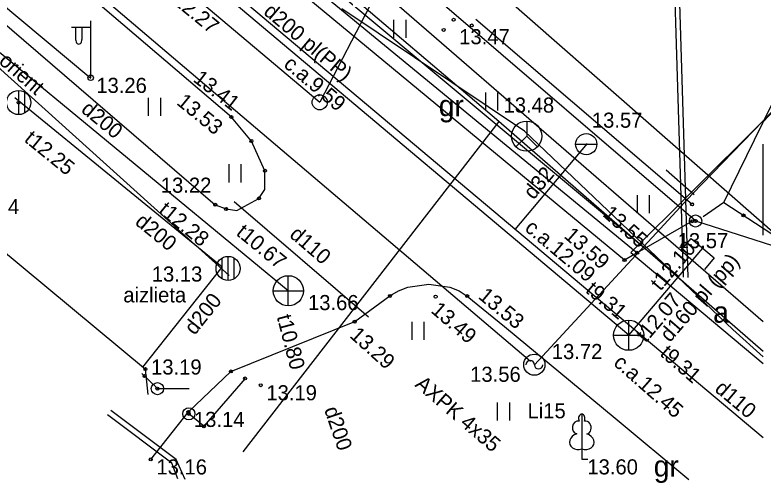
# Model space of a CAD drawing. Extents: x 503877 to 504025, y 304562 to 304725.
# Drawn here: x 503975.24 to 504000, y 304561.64 to 304577.15 of the extents above; entities that cross this region are included whole.
import ezdxf

# ---------------------------------------------------------------- set-up
doc = ezdxf.new("R2010")
doc.units = 0
for name, color, linetype in [('10', 7, 'Continuous'), ('20', 7, 'Continuous'), ('25', 7, 'Continuous'), ('APGS_ACRL_####_####_#', 7, 'Continuous'), ('APGS_ACRL_####_TKST_#', 7, 'Continuous'), ('APGS_ELEM_####_####_#', 7, 'Continuous'), ('APGS_VADP_ZSPR_####_#', 7, 'Continuous'), ('APGS_VADP_ZSPR_TKST_#', 7, 'Continuous'), ('BUVE_BDET_####_####_#', 7, 'Continuous'), ('BUVE_EKAS_####_####_#', 7, 'Continuous'), ('CELI_CAPM_####_####_#', 7, 'Continuous'), ('CELI_CMAL_####_####_#', 7, 'Continuous'), ('CELI_CSEG_####_TKST_#', 7, 'Continuous'), ('CELI_TAKA_####_####_#', 7, 'Continuous'), ('ELEK_VADP_ZSPR_####_#', 7, 'Continuous'), ('ELEK_VADV_ZSPR_####_#', 7, 'Continuous'), ('GAZE_ELEM_####_####_#', 7, 'Continuous'), ('GAZE_ELEM_####_TKST_#', 7, 'Continuous'), ('GAZE_VADP_VSP1_####_#', 7, 'Continuous'), ('GAZE_VADP_VSP2_####_#', 7, 'Continuous'), ('Level 46', 7, 'Continuous'), ('LKAN_ELEM_####_####_#', 7, 'Continuous'), ('LKAN_ELEM_PAST_TKST_#', 7, 'Continuous'), ('LKAN_VADP_PAST_####_#', 7, 'Continuous'), ('LKAN_VADP_PAST_TKST_#', 7, 'Continuous'), ('NORB_ELEM_####_####_#', 7, 'Continuous'), ('NORB_ZOGS_BARJ_####_#', 7, 'Continuous'), ('NORB_ZOGS_ZSTP_####_#', 7, 'Continuous'), ('RAMI_PROB_####_####_#', 7, 'Continuous'), ('RELJ_AATZ_####_TKST_#', 7, 'Continuous'), ('RELJ_ELEM_####_####_#', 7, 'Continuous'), ('SAKK_ELEM_####_####_#', 7, 'Continuous'), ('SAKK_ELEM_####_TKST_#', 7, 'Continuous'), ('SAKK_KKAN_####_####_#', 7, 'Continuous'), ('SAKT_VADP_KABE_####_#', 7, 'Continuous'), ('SAKT_VADP_NEDR_####_#', 7, 'Continuous'), ('SKAN_ELEM_####_####_#', 7, 'Continuous'), ('SKAN_ELEM_PAST_TKST_#', 7, 'Continuous'), ('SKAN_VADP_PAST_####_#', 7, 'Continuous'), ('SKAN_VADP_PAST_####_I', 7, 'Continuous'), ('SKAN_VADP_PAST_TKST_#', 7, 'Continuous'), ('SKAN_VADP_PAST_TKST_I', 7, 'Continuous'), ('SKAN_VADP_SPDK_TKST_I', 7, 'Continuous'), ('TERT_DIAM_####_TKST_#', 7, 'Continuous'), ('TERT_DZOG_####_####_#', 7, 'Continuous'), ('TERT_ELEM_####_####_#', 7, 'Continuous'), ('TERT_KOKR_####_####_#', 7, 'Continuous'), ('TERT_KONT_####_####_#', 7, 'Continuous'), ('UDTK_ELEM_####_####_#', 7, 'Continuous'), ('UDTK_ELEM_####_TKST_#', 7, 'Continuous'), ('UDTK_VADP_NEDR_####_#', 7, 'Continuous'), ('UDTK_VADP_NEDR_TKST_#', 7, 'Continuous'), ('UDTK_VADP_UDEN_####_I', 7, 'Continuous'), ('UDTK_VADP_UDEN_TKST_I', 7, 'Continuous')]:
    doc.layers.add(name, color=color, linetype=linetype)

msp = doc.modelspace()

# ---------------------------------------------------------------- linework, layer by layer
at = {"layer": '10'}
msp.add_circle((503985.325, 304574.255), 0.25, dxfattribs=at)
at = {"layer": '20'}
msp.add_line((503987.744, 304578.935), (503985.325, 304574.255), dxfattribs=at)
at = {"layer": '25'}
msp.add_line((503924.947, 304625.297), (503985.325, 304574.255), dxfattribs=at)
at = {"layer": 'APGS_ACRL_####_####_#'}
msp.add_line((503982.497, 304570.972), (503986.938, 304567.15), dxfattribs=at)
at = {"layer": 'APGS_ELEM_####_####_#'}
for p, q in [((503977.744, 304576.733), (503977.109, 304576.728)), ((503977.244, 304576.729), (503977.244, 304576.337)), ((503977.454, 304576.731), (503977.454, 304576.337)), ((503977.744, 304575.066), (503977.744, 304576.949))]:
    msp.add_line(p, q, dxfattribs=at)
msp.add_circle((503977.744, 304575.066), 0.09, dxfattribs=at)
msp.add_ellipse((503977.349, 304576.337), major_axis=(0, 0.151), ratio=0.695971, start_param=1.570796, end_param=4.712389, dxfattribs=at)
at = {"layer": 'APGS_VADP_ZSPR_####_#'}
msp.add_line((503955.752, 304593.437), (503977.746, 304575.06), dxfattribs=at)
at = {"layer": 'BUVE_BDET_####_####_#'}
msp.add_line((503979.642, 304564.578), (503979.555, 304565.414), dxfattribs=at)
at = {"layer": 'BUVE_EKAS_####_####_#'}
msp.add_line((503973.411, 304570.524), (503979.555, 304565.414), dxfattribs=at)
at = {"layer": 'CELI_CAPM_####_####_#'}
for p, q in [((503982.4, 304573.765), (503968.656, 304585.514)), ((503983.065, 304572.971), (503982.4, 304573.765)), ((503983.513, 304571.985), (503983.065, 304572.971)), ((503983.513, 304571.371), (503983.513, 304571.985)), ((503983.314, 304571.071), (503983.513, 304571.371))]:
    msp.add_line(p, q, dxfattribs=at)
at = {"layer": 'CELI_CMAL_####_####_#'}
for p, q in [((503967.389, 304583.318), (503981.868, 304570.859)), ((503995.414, 304569.03), (503982.055, 304580.09)), ((503982.586, 304570.674), (503983.314, 304571.071)), ((503981.868, 304570.859), (503982.224, 304570.722)), ((503998.706, 304570.932), (503998.022, 304570.456)), ((503998.706, 304570.932), (504000, 304570.084)), ((503982.224, 304570.722), (503982.586, 304570.674)), ((503997.655, 304570.314), (503995.836, 304569.27)), ((503999.782, 304570.227), (504000, 304570.084)), ((504000, 304570.084), (504002.603, 304568.379)), ((503995.836, 304569.27), (503995.414, 304569.03)), ((503987.93, 304568.004), (503988.247, 304568.125)), ((503988.247, 304568.125), (503988.939, 304568.227)), ((503988.939, 304568.227), (503989.627, 304568.134)), ((503989.627, 304568.134), (503989.937, 304568.011)), ((503986.483, 304566.989), (503987.649, 304567.838)), ((503987.649, 304567.838), (503987.93, 304568.004)), ((503989.937, 304568.011), (503990.209, 304567.835)), ((503990.209, 304567.835), (503991.439, 304566.83)), ((503982.384, 304565.337), (503986.483, 304566.989)), ((503991.439, 304566.83), (503995.105, 304563.792)), ((503980.976, 304563.999), (503982.384, 304565.337)), ((503979.734, 304562.425), (503980.976, 304563.999)), ((503995.105, 304563.792), (503997.539, 304561.754))]:
    msp.add_line(p, q, dxfattribs=at)
at = {"layer": 'CELI_TAKA_####_####_#'}
msp.add_line((503982.372, 304580.35), (503995.836, 304569.27), dxfattribs=at)
at = {"layer": 'ELEK_VADP_ZSPR_####_#'}
for p, q in [((503980.425, 304562.304), (503978.298, 304563.903)), ((503980.578, 304562.426), (503978.415, 304564.044)), ((503980.873, 304561.755), (503980.578, 304562.426)), ((503980.629, 304561.786), (503980.425, 304562.304))]:
    msp.add_line(p, q, dxfattribs=at)
at = {"layer": 'ELEK_VADV_ZSPR_####_#'}
msp.add_line((503972.501, 304590.85), (504000, 304566.991), dxfattribs=at)
at = {"layer": 'GAZE_ELEM_####_####_#'}
msp.add_circle((503992.43, 304565.562), 0.35, dxfattribs=at)
for centre, start, end in [((503992.29, 304565.562), 0, 180), ((503992.57, 304565.562), 180, 0)]:
    msp.add_arc(centre, 0.14, start, end, dxfattribs=at)
at = {"layer": 'GAZE_VADP_VSP1_####_#'}
for p, q in [((504002.447, 304576.169), (504000, 304573.64)), ((504000, 304573.604), (504000.37, 304573.991)), ((504000, 304573.64), (503997.664, 304571.226))]:
    msp.add_line(p, q, dxfattribs=at)
at = {"layer": 'GAZE_VADP_VSP2_####_#'}
for p, q in [((503971.829, 304583.093), (503992.301, 304565.684)), ((503997.664, 304571.225), (503992.43, 304565.562))]:
    msp.add_line(p, q, dxfattribs=at)
at = {"layer": 'Level 46'}
msp.add_line((503943.333, 304620.019), (504006.701, 304564.361), dxfattribs=at)
at = {"layer": 'LKAN_ELEM_####_####_#'}
for p, q in [((503975.36, 304573.848), (503975.36, 304574.648)), ((503975.56, 304573.902), (503975.56, 304574.594)), ((503982.093, 304568.405), (503982.093, 304569.097)), ((503982.293, 304568.351), (503982.293, 304569.151)), ((503982.493, 304568.405), (503982.493, 304569.097))]:
    msp.add_line(p, q, dxfattribs=at)
for centre in [(503975.36, 304574.248), (503982.293, 304568.751)]:
    msp.add_circle(centre, 0.4, dxfattribs=at)
at = {"layer": 'LKAN_VADP_PAST_####_#'}
for p, q in [((503982.094, 304568.792), (503975.237, 304574.404)), ((503979.472, 304565.483), (503982.094, 304568.792))]:
    msp.add_line(p, q, dxfattribs=at)
at = {"layer": 'NORB_ELEM_####_####_#'}
for centre in [(503997.768, 304570.323), (503979.953, 304564.768), (503980.991, 304563.932)]:
    msp.add_circle(centre, 0.202, dxfattribs=at)
at = {"layer": 'NORB_ZOGS_BARJ_####_#'}
for p, q in [((503997.768, 304570.323), (504000, 304569.607)), ((504000, 304569.607), (504000.857, 304569.333)), ((503979.953, 304564.768), (503980.999, 304564.768))]:
    msp.add_line(p, q, dxfattribs=at)
at = {"layer": 'NORB_ZOGS_ZSTP_####_#'}
for p, q in [((503997.768, 304570.323), (503987.718, 304578.958)), ((503979.438, 304565.273), (503979.953, 304564.768)), ((503982.856, 304565.105), (503981.489, 304563.521)), ((503981.489, 304563.521), (503980.991, 304563.932))]:
    msp.add_line(p, q, dxfattribs=at)
at = {"layer": 'RAMI_PROB_####_####_#'}
msp.add_line((504000, 304569.849), (504000, 304572.866), dxfattribs=at)
at = {"layer": 'RELJ_ELEM_####_####_#'}
for centre in [(503989.757, 304576.989), (503990.359, 304576.8), (503989.429, 304576.655), (503975.36, 304574.248), (503982.4, 304573.765), (503983.065, 304572.971), (503983.513, 304571.985), (503983.314, 304571.071), (503981.868, 304570.859), (503997.65, 304570.875), (503982.224, 304570.722), (503999.353, 304570.508), (503997.655, 304570.314), (503997.768, 304570.323), (503995.836, 304569.27), (503995.414, 304569.03), (503987.649, 304567.838), (503989.163, 304567.817), (503990.209, 304567.835), (503986.483, 304566.989), (503979.555, 304565.414), (503982.384, 304565.337), (503979.529, 304565.184), (503982.856, 304565.105), (503983.373, 304564.883), (503979.953, 304564.768), (503980.976, 304563.999), (503980.991, 304563.932), (503981.489, 304563.521), (503979.734, 304562.425)]:
    msp.add_circle(centre, 0.05, dxfattribs=at)
at = {"layer": 'SAKK_ELEM_####_####_#'}
msp.add_line((503992.176, 304573.133), (503992.53, 304572.779), dxfattribs=at)
msp.add_lwpolyline([(503992.176, 304573.633), (503992.176, 304573.133), (503991.822, 304572.779)], dxfattribs=at)
msp.add_circle((503992.176, 304573.133), 0.5, dxfattribs=at)
at = {"layer": 'SAKK_KKAN_####_####_#'}
for p, q in [((503992.108, 304573.299), (503986.057, 304577.347)), ((503998.999, 304566.726), (503992.108, 304573.299)), ((504000, 304565.824), (503998.999, 304566.726))]:
    msp.add_line(p, q, dxfattribs=at)
at = {"layer": 'SAKT_VADP_KABE_####_#'}
for p, q in [((503991.251, 304573.616), (503971.653, 304590.306)), ((503991.251, 304573.616), (503982.785, 304562.67)), ((504000, 304565.996), (503991.251, 304573.616)), ((503997.62, 304571.269), (503995.622, 304569.281)), ((503995.622, 304569.281), (504000, 304565.603))]:
    msp.add_line(p, q, dxfattribs=at)
for points in [[(503997.274, 304571.519), (503996.598, 304593.747)], [(503997.428, 304571.411), (503996.759, 304593.401)], [(504005.756, 304579.363), (504000, 304573.637)], [(504000, 304573.637), (503997.62, 304571.269)]]:
    msp.add_lwpolyline(points, dxfattribs=at)
at = {"layer": 'SAKT_VADP_NEDR_####_#'}
for p, q in [((503997.217, 304568.475), (503924.507, 304629.123)), ((503997.367, 304568.463), (503997.274, 304571.519)), ((503997.518, 304568.451), (503997.428, 304571.411))]:
    msp.add_line(p, q, dxfattribs=at)
at = {"layer": 'SKAN_ELEM_####_####_#'}
for p, q in [((503984.286, 304567.511), (503984.286, 304568.511)), ((503983.786, 304568.011), (503984.786, 304568.011)), ((503995.552, 304566.038), (503995.552, 304567.038)), ((503995.052, 304566.538), (503996.052, 304566.538))]:
    msp.add_line(p, q, dxfattribs=at)
msp.add_lwpolyline([(503997.3, 304569.364), (503997.624, 304569.745), (503998.386, 304569.097), (503998.062, 304568.716)], dxfattribs=at)
for centre in [(503984.286, 304568.011), (503995.552, 304566.538)]:
    msp.add_circle(centre, 0.5, dxfattribs=at)
at = {"layer": 'SKAN_VADP_PAST_####_#'}
msp.add_line((503984.286, 304568.011), (503971.339, 304578.696), dxfattribs=at)
at = {"layer": 'SKAN_VADP_PAST_####_I'}
for q in [(503973.287, 304585.319), (503998.005, 304569.421)]:
    msp.add_line((503995.552, 304566.538), q, dxfattribs=at)
at = {"layer": 'TERT_DZOG_####_####_#'}
msp.add_lwpolyline([(503996.788, 304572.019), (503997.718, 304571.201)], dxfattribs=at)
at = {"layer": 'TERT_ELEM_####_####_#'}
for p, q in [((503987.784, 304576.391), (503987.784, 304576.991)), ((503988.184, 304576.391), (503988.184, 304576.991)), ((503990.819, 304573.982), (503990.819, 304574.582)), ((503991.219, 304573.982), (503991.219, 304574.582)), ((503979.661, 304573.802), (503979.661, 304574.402)), ((503980.061, 304573.802), (503980.061, 304574.402)), ((503982.329, 304571.603), (503982.329, 304572.203)), ((503982.729, 304571.603), (503982.729, 304572.203)), ((503995.843, 304570.578), (503995.843, 304571.178)), ((503996.243, 304570.578), (503996.243, 304571.178)), ((503988.388, 304566.383), (503988.388, 304566.983)), ((503988.788, 304566.383), (503988.788, 304566.983)), ((503991.214, 304563.712), (503991.214, 304564.312)), ((503991.614, 304563.712), (503991.614, 304564.312)), ((503993.999, 304562.774), (503993.999, 304562.427)), ((503993.999, 304562.427), (503994.199, 304562.427))]:
    msp.add_line(p, q, dxfattribs=at)
for points in [[(503993.999, 304563.927), (503993.999, 304562.774)], [(503994.089, 304563.695), (503994.088, 304563.696)]]:
    msp.add_lwpolyline(points, dxfattribs=at)
for centre, major_axis, ratio, start_param, end_param in [((503993.999, 304563.777), (0, -0.15), 0.707107, 3.14537, 5.287485), ((503993.999, 304563.777), (0, -0.15), 0.707107, 0.995701, 3.137816), ((503993.871, 304563.482), (-0.039, -0.212), 0.861323, 3.141593, 6.283185), ((503994.127, 304563.482), (0.039, -0.212), 0.861323, 0, 3.141593), ((503993.909, 304563.02), (0.307, 0.095), 0.814445, 1.570796, 4.752015), ((503994.089, 304563.02), (-0.307, 0.095), 0.814445, 1.531171, 4.712389)]:
    msp.add_ellipse(centre, major_axis=major_axis, ratio=ratio, start_param=start_param, end_param=end_param, dxfattribs=at)
at = {"layer": 'TERT_KOKR_####_####_#'}
msp.add_line((503990.492, 304577.005), (503997.65, 304570.875), dxfattribs=at)
at = {"layer": 'TERT_KONT_####_####_#'}
for p, q in [((504000, 304573.594), (504001.484, 304576.646)), ((503999.718, 304573.013), (504000, 304573.594)), ((503998.706, 304570.932), (503999.718, 304573.013))]:
    msp.add_line(p, q, dxfattribs=at)
at = {"layer": 'UDTK_ELEM_####_####_#'}
msp.add_line((503993.797, 304572.867), (503994.499, 304572.867), dxfattribs=at)
msp.add_circle((503994.148, 304572.867), 0.351, dxfattribs=at)
at = {"layer": 'UDTK_VADP_NEDR_####_#'}
msp.add_line((503965.385, 304583.819), (503982.325, 304568.514), dxfattribs=at)
at = {"layer": 'UDTK_VADP_UDEN_####_I'}
for p, q in [((504000, 304563.139), (503968.511, 304589.634)), ((503991.792, 304570.046), (503994.186, 304572.891))]:
    msp.add_line(p, q, dxfattribs=at)

# ---------------------------------------------------------------- texts
at = {"layer": 'APGS_ACRL_####_TKST_#'}
msp.add_text('d110', height=0.5, rotation=319.2866, dxfattribs=at).set_placement((503984.295, 304569.82))
at = {"layer": 'APGS_VADP_ZSPR_TKST_#'}
msp.add_text('AXPK 4x35', height=0.5, rotation=319.2866, dxfattribs=at).set_placement((503988.449, 304564.864))
at = {"layer": 'CELI_CSEG_####_TKST_#'}
for s, p in [('gr', (503989.266, 304573.795)), ('a', (503998.348, 304566.954)), ('gr', (503996.382, 304561.852))]:
    msp.add_text(s, height=0.7, dxfattribs=at).set_placement(p)
at = {"layer": 'GAZE_ELEM_####_TKST_#'}
msp.add_text(' 13.56', height=0.5, dxfattribs=at).set_placement((503990.12, 304564.995))
at = {"layer": 'LKAN_ELEM_PAST_TKST_#'}
msp.add_text(' 13.13', height=0.5, dxfattribs=at).set_placement((503979.58, 304568.316))
at = {"layer": 'LKAN_VADP_PAST_TKST_#'}
for s, rotation, p in [('t12.25', 320.8644, (503975.511, 304572.98)), ('t12.28', 320.7019, (503979.962, 304570.622)), ('d200', 320.7019, (503979.18, 304570.237)), ('d200', 51.5989, (503981.186, 304566.515))]:
    msp.add_text(s, height=0.5, rotation=rotation, dxfattribs=at).set_placement(p)
at = {"layer": 'RELJ_AATZ_####_TKST_#'}
for s, p in [(' 13.47', (503989.757, 304576.179)), (' 13.26', (503977.744, 304574.566)), (' 13.22', (503979.879, 304571.259)), (' 13.24', (503973.519, 304570.549)), (' 13.57', (503996.989, 304569.423)), (' 13.19', (503979.557, 304565.236)), (' 13.19', (503983.373, 304564.383)), (' 13.14', (503980.976, 304563.499)), (' 13.16', (503979.734, 304561.925)), (' 13.60', (503993.999, 304561.927))]:
    msp.add_text(s, height=0.5, dxfattribs=at).set_placement(p)
for s, rotation, p in [(' 13.41', 322.3262, (503980.956, 304575.083)), (' 13.53', 320.8266, (503980.415, 304574.323)), (' 13.55', 318.2274, (503994.521, 304570.637)), (' 13.59', 318.8465, (503993.243, 304569.913)), (' 13.53', 320.1866, (503990.4, 304567.901)), (' 13.49', 319.182, (503988.836, 304567.439)), (' 13.29', 318.0213, (503986.149, 304566.617))]:
    msp.add_text(s, height=0.5, rotation=rotation, dxfattribs=at).set_placement(p)
at = {"layer": 'SAKK_ELEM_####_TKST_#'}
msp.add_text(' 13.48', height=0.5, dxfattribs=at).set_placement((503991.226, 304573.913))
at = {"layer": 'SKAN_ELEM_PAST_TKST_#'}
for s, p in [('aizlieta', (503978.823, 304567.625)), ('13.66', (503984.937, 304567.37)), (' 13.72', (503992.822, 304565.748))]:
    msp.add_text(s, height=0.5, dxfattribs=at).set_placement(p)
at = {"layer": 'SKAN_VADP_PAST_TKST_#'}
for s, rotation, p in [('d200', 320.4757, (503977.395, 304573.961)), ('t10.67', 320.4676, (503982.527, 304569.883)), ('t10.80', 284.5789, (503983.899, 304567.155)), ('d200', 288.7429, (503985.467, 304564.081))]:
    msp.add_text(s, height=0.5, rotation=rotation, dxfattribs=at).set_placement(p)
at = {"layer": 'SKAN_VADP_PAST_TKST_I'}
for s, rotation, p in [('d200 pl(PP)', 319.8517, (503983.433, 304577.202)), ('c.a.9.59', 319.8517, (503984.098, 304575.457)), ('t12.10', 49.6072, (503996.603, 304567.981)), ('d160 pl (pp)', 49.0774, (503996.914, 304566.278)), ('t9.31', 319.8517, (503994.09, 304567.987)), ('t12.07', 49.6072, (503996.119, 304566.261)), ('t9.31', 318.9898, (503996.556, 304565.891))]:
    msp.add_text(s, height=0.5, rotation=rotation, dxfattribs=at).set_placement(p)
at = {"layer": 'SKAN_VADP_SPDK_TKST_I'}
for s, rotation, p in [('c.a.12.27', 320.6077, (503979.603, 304578.237)), ('c.a.12.45', 318.7343, (503995.018, 304565.573))]:
    msp.add_text(s, height=0.5, rotation=rotation, dxfattribs=at).set_placement(p)
at = {"layer": 'TERT_DIAM_####_TKST_#'}
msp.add_text('Li15', height=0.5, dxfattribs=at).set_placement((503992.204, 304563.786))
at = {"layer": 'UDTK_ELEM_####_TKST_#'}
msp.add_text(' 13.57', height=0.5, dxfattribs=at).set_placement((503994.148, 304573.413))
at = {"layer": 'UDTK_VADP_NEDR_TKST_#'}
msp.add_text('orient', height=0.5, rotation=318.7792, dxfattribs=at).set_placement((503974.672, 304575.569))
at = {"layer": 'UDTK_VADP_UDEN_TKST_I'}
for s, rotation, p in [('d32', 49.9227, (503992.401, 304571.002)), ('c.a.12.09', 319.9227, (503992.079, 304570.034)), ('d110', 319.9227, (503998.368, 304564.708))]:
    msp.add_text(s, height=0.5, rotation=rotation, dxfattribs=at).set_placement(p)

doc.saveas('drawing.dxf')
